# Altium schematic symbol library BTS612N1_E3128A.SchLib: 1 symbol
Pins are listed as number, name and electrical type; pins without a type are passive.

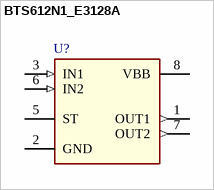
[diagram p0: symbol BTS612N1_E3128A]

## BTS612N1_E3128A
designator U?  (value not drawn)
Smart Two Channel High-Side Power Switch; Manufacturer: Infineon Technologies
footprint TO127P1500X440-7_8N
pins: 1 OUT1 (out) "Output 1", 2 GND (power) "Logic Ground", 3 IN1 (in) "Input 1", 5 ST "Diagnostic feedback", 6 IN2 (in) "Input 2", 7 OUT2 (out) "Output 2", 8 VBB (power) "Positive power supply voltage"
